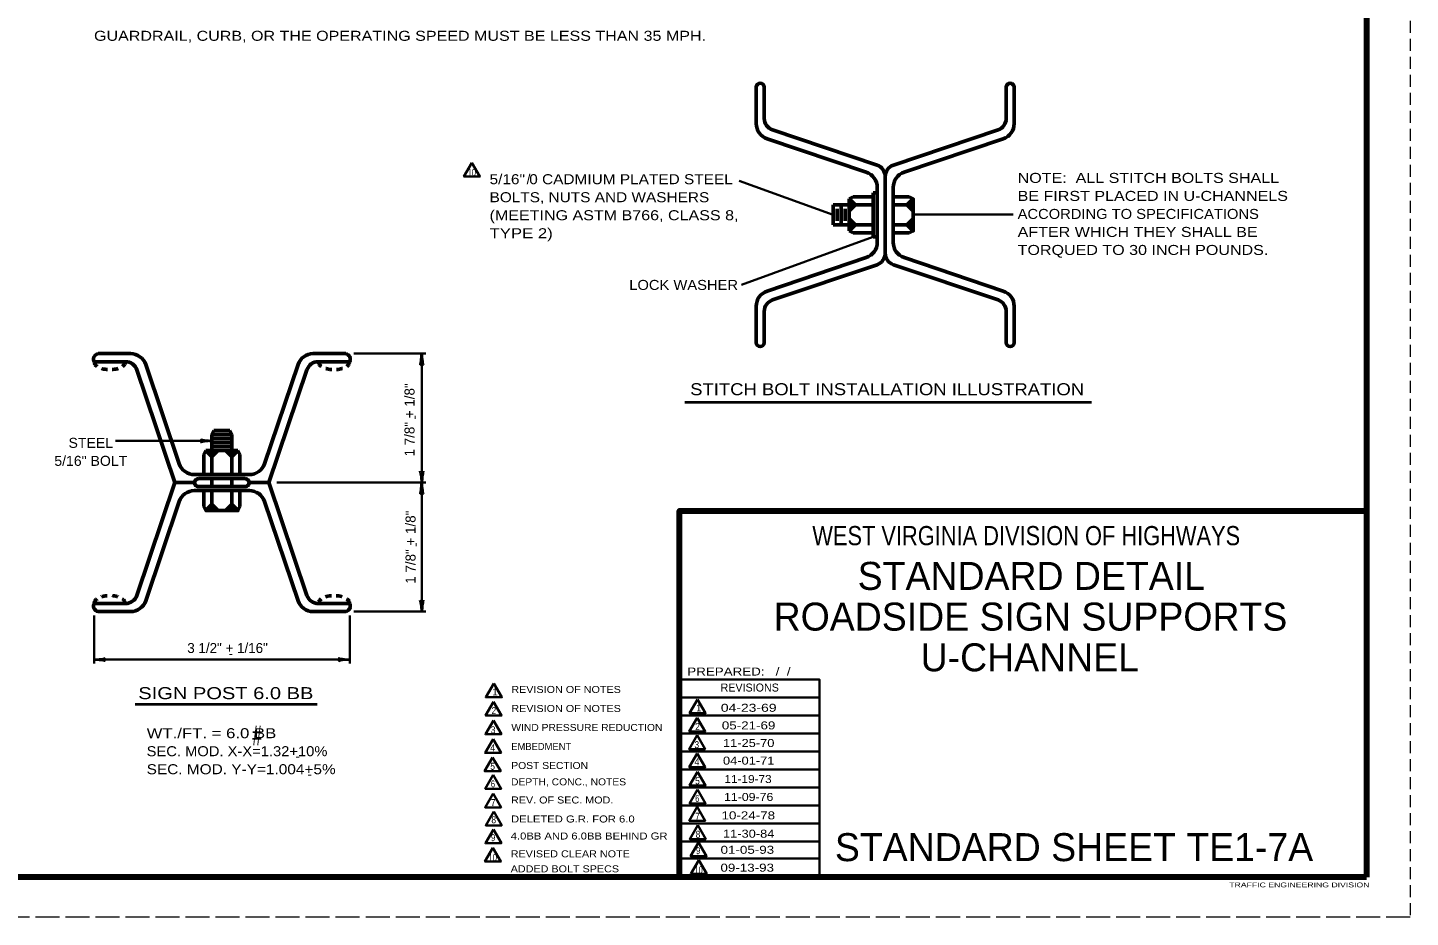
# Model space of a CAD drawing. Extents: x -2 to 678, y -1 to 439.
# Drawn here: x 332.9 to 678.3, y -0.7 to 221.6 of the extents above; entities that cross this region are included whole.
import ezdxf
from ezdxf.enums import TextEntityAlignment as Align

# ---------------------------------------------------------------- set-up
doc = ezdxf.new("R2010")
doc.units = 0
for name, pattern in [('LONG_DASHED', [7.5, 6, -1.5]), ('MEDIUM_DASHED', [4.5, 3, -1.5]), ('SHORT_DASHED', [2.7, 1.5, -1.2])]:
    doc.linetypes.add(name, pattern=pattern)
doc.layers.add('1', color=7, linetype='Continuous', lineweight=53)
doc.layers.add('61', color=7, linetype='Continuous', lineweight=35)

msp = doc.modelspace()

# ---------------------------------------------------------------- linework, layer by layer
at = {"layer": '1', "linetype": 'MEDIUM_DASHED', "lineweight": 13}
msp.add_line((678.327, 439.301), (678.307, -0.719), dxfattribs=at)
at = {"layer": '1'}
for p, q in [((514.897, 197.583), (514.897, 206.711)), ((516.897, 198.865), (516.897, 206.711)), ((577.341, 198.865), (577.341, 206.711)), ((579.341, 197.583), (579.341, 206.711)), ((542.398, 185.438), (517.619, 193.793)), ((545.078, 187.208), (518.939, 196.023)), ((549.161, 187.208), (575.3, 196.023)), ((551.841, 185.438), (576.619, 193.793)), ((547.119, 165.174), (547.119, 184.366)), ((545.119, 180.27), (544.119, 180.27)), ((544.119, 180.27), (544.119, 169.27)), ((545.119, 167.892), (545.119, 181.648)), ((549.119, 167.892), (549.119, 181.648)), ((534.119, 172.27), (534.119, 177.27)), ((535.119, 173.27), (535.119, 176.27)), ((536.119, 172.27), (536.119, 177.27)), ((537.119, 173.27), (537.119, 176.27)), ((538.119, 178.77), (539.119, 179.27)), ((538.119, 170.77), (538.119, 178.77)), ((539.119, 179.27), (544.119, 179.27)), ((549.119, 179.27), (553.119, 179.27)), ((549.119, 177.27), (554.119, 177.27)), ((554.119, 178.77), (553.119, 179.27)), ((554.119, 170.77), (554.119, 178.77)), ((538.119, 170.77), (539.119, 170.27)), ((539.119, 170.27), (544.119, 170.27)), ((549.119, 172.27), (554.119, 172.27)), ((549.119, 170.27), (553.119, 170.27)), ((554.119, 170.77), (553.119, 170.27)), ((545.119, 169.27), (544.119, 169.27)), ((542.398, 164.102), (517.619, 155.747)), ((551.841, 164.102), (576.619, 155.747)), ((545.078, 162.332), (518.939, 153.517)), ((549.161, 162.332), (575.3, 153.517)), ((514.897, 151.957), (514.897, 142.829)), ((516.897, 150.675), (516.897, 142.829)), ((577.341, 150.675), (577.341, 142.829)), ((579.341, 151.957), (579.341, 142.829)), ((358.566, 140.102), (350.438, 140.102)), ((404.193, 140.102), (412.32, 140.102)), ((357.284, 138.102), (349.438, 138.102)), ((369.629, 107.88), (360.127, 136.061)), ((370.711, 112.602), (362.356, 137.38)), ((392.047, 112.602), (400.402, 137.38)), ((393.129, 107.88), (402.632, 136.061)), ((405.475, 138.102), (413.32, 138.102)), ((379.379, 120.88), (378.879, 119.88)), ((378.879, 119.88), (383.879, 119.88)), ((378.879, 118.88), (383.879, 118.88)), ((378.879, 117.88), (383.879, 117.88)), ((379.379, 120.88), (383.379, 120.88)), ((383.379, 120.88), (383.879, 119.88)), ((377.379, 115.88), (376.879, 114.88)), ((376.879, 114.88), (376.879, 109.88)), ((377.379, 115.88), (385.379, 115.88)), ((378.879, 116.88), (383.656, 116.88)), ((385.379, 115.88), (385.879, 114.88)), ((385.879, 114.88), (385.879, 109.88)), ((369.629, 107.88), (360.127, 79.7)), ((369.629, 107.88), (374.577, 107.88)), ((374.502, 109.88), (388.257, 109.88)), ((375.629, 108.88), (387.129, 108.88)), ((378.879, 108.88), (378.879, 106.88)), ((383.879, 108.88), (383.879, 106.88)), ((388.182, 107.88), (393.129, 107.88)), ((393.129, 107.88), (402.632, 79.7)), ((374.502, 105.88), (388.257, 105.88)), ((375.629, 106.88), (387.129, 106.88)), ((376.879, 105.88), (376.879, 101.88)), ((378.879, 105.88), (378.879, 100.88)), ((383.879, 105.88), (383.879, 100.88)), ((385.879, 105.88), (385.879, 101.88)), ((370.711, 103.159), (362.356, 78.38)), ((377.379, 100.88), (376.879, 101.88)), ((377.379, 100.88), (385.379, 100.88)), ((385.379, 100.88), (385.879, 101.88)), ((392.047, 103.159), (400.402, 78.38)), ((357.284, 77.658), (349.438, 77.658)), ((405.475, 77.658), (413.32, 77.658)), ((358.566, 75.658), (350.438, 75.658)), ((404.193, 75.658), (412.32, 75.658))]:
    msp.add_line(p, q, dxfattribs=at)
at = {"layer": '1', "lineweight": 35}
for p, q in [((534.119, 174.77), (510.627, 183.32)), ((554.083, 174.907), (579.083, 174.907)), ((544.119, 169.27), (511.23, 157.299)), ((414.32, 140.102), (432.32, 140.102)), ((378.811, 118.315), (354.811, 118.315)), ((395.129, 107.88), (432.32, 107.88)), ((349.438, 74.658), (349.438, 62.658)), ((413.32, 74.658), (413.32, 62.658)), ((414.32, 75.658), (432.32, 75.658)), ((349.438, 63.658), (413.32, 63.658)), ((530.707, 54.201), (495.727, 54.201)), ((530.707, 49.701), (495.727, 49.701)), ((530.707, 45.201), (495.727, 45.201)), ((530.707, 40.681), (495.727, 40.681)), ((530.707, 36.201), (495.727, 36.201)), ((530.707, 31.721), (495.727, 31.721)), ((530.707, 27.221), (495.727, 27.221)), ((530.707, 22.721), (495.727, 22.721)), ((530.707, 18.201), (495.727, 18.201)), ((530.707, 13.968), (495.727, 13.968))]:
    msp.add_line(p, q, dxfattribs=at)
at = {"layer": '1', "lineweight": 40}
for p, q in [((497.072, 127.975), (598.672, 127.975)), ((359.751, 52.487), (405.219, 52.487))]:
    msp.add_line(p, q, dxfattribs=at)
at = {"layer": '1', "lineweight": 35}
for points in [[(443.859, 187.82), (441.859, 184.356), (445.859, 184.356)], [(449.331, 57.723), (447.331, 54.259), (451.331, 54.259)], [(449.271, 53.147), (447.271, 49.683), (451.271, 49.683)], [(500.227, 53.724), (498.227, 50.26), (502.227, 50.26)], [(449.21, 48.458), (447.21, 44.994), (451.21, 44.994)], [(500.166, 49.148), (498.166, 45.684), (502.166, 45.684)], [(449.124, 43.796), (447.124, 40.332), (451.124, 40.332)], [(500.106, 44.752), (498.106, 41.288), (502.106, 41.288)], [(449.038, 39.22), (447.038, 35.756), (451.038, 35.756)], [(500.166, 40.236), (498.166, 36.772), (502.166, 36.772)], [(449.184, 34.837), (447.184, 31.373), (451.184, 31.373)], [(500.227, 35.66), (498.227, 32.196), (502.227, 32.196)], [(500.227, 31.205), (498.227, 27.741), (502.227, 27.741)], [(449.124, 30.209), (447.124, 26.745), (451.124, 26.745)], [(449.318, 25.706), (447.318, 22.242), (451.318, 22.242)], [(500.166, 26.87), (498.166, 23.405), (502.166, 23.405)], [(449.244, 21.235), (447.244, 17.77), (451.244, 17.77)], [(500.287, 22.294), (498.287, 18.829), (502.287, 18.829)], [(500.47, 17.989), (498.47, 14.525), (502.47, 14.525)], [(449.098, 16.649), (447.098, 13.184), (451.098, 13.184)], [(500.521, 13.557), (498.521, 10.093), (502.521, 10.093)]]:
    msp.add_lwpolyline(points, close=True, dxfattribs=at)
at = {"layer": '1'}
for points in [[(534.119, 177.27), (538.119, 177.27), (544.119, 177.27)], [(534.119, 172.27), (538.119, 172.27), (544.119, 172.27)], [(378.879, 119.88), (378.879, 115.88), (378.879, 109.88)], [(383.879, 119.88), (383.879, 115.88), (383.879, 109.88)]]:
    msp.add_lwpolyline(points, dxfattribs=at)
for points in [[(538.119, 178.77), (538.119, 175.77), (539.619, 177.27)], [(554.119, 175.77), (552.619, 177.27), (554.119, 178.77)], [(538.119, 170.77), (538.119, 173.77), (539.619, 172.27)], [(552.619, 172.27), (554.119, 170.77), (554.119, 173.77)], [(377.379, 115.88), (380.379, 115.88), (378.879, 114.38)], [(385.379, 115.88), (382.379, 115.88), (383.879, 114.38)], [(378.879, 102.38), (377.379, 100.88), (380.379, 100.88)], [(382.379, 100.88), (383.879, 102.38), (385.379, 100.88)]]:
    msp.add_lwpolyline(points, close=True, dxfattribs=at)
at = {"layer": '1', "lineweight": 35}
for points in [[(431.32, 140.102), (431.32, 107.88), (431.32, 75.658)], [(530.707, 9.221), (530.707, 58.681), (495.727, 58.681)]]:
    msp.add_lwpolyline(points, dxfattribs=at)
at = {"layer": '1', "lineweight": 158}
msp.add_lwpolyline([(495.707, 9.261), (495.707, 100.841), (667.367, 100.841)], dxfattribs=at)
at = {"layer": '1'}
for centre, radius, start, end in [((515.897, 206.664), 1.001, 2.66716, 177.33283), ((578.341, 206.664), 1.001, 2.66716, 177.33283), ((518.897, 197.584), 4, 180, 251.36561), ((519.897, 198.865), 3, 180, 251.36548), ((574.341, 198.865), 3, 288.63452, 0), ((575.341, 197.584), 4, 288.63439, 360), ((544.119, 184.366), 3, 0, 71.36649), ((550.119, 184.366), 3, 108.63574, 180), ((541.119, 181.648), 4, 0, 71.36535), ((553.119, 181.648), 4, 108.63465, 180), ((541.119, 167.892), 4, 288.63525, 0), ((553.119, 167.892), 4, 180, 251.36475), ((544.119, 165.174), 3, 288.63393, 0), ((550.119, 165.174), 3, 180, 251.36641), ((518.897, 151.957), 4, 108.63408, 180), ((575.341, 151.957), 4, 0, 71.36592), ((519.897, 150.675), 3, 108.63464, 180), ((574.341, 150.675), 3, 0, 71.36536), ((515.897, 142.876), 1.001, 182.66717, 357.33284), ((578.341, 142.876), 1.001, 182.66717, 357.33284), ((350.703, 138.72), 1.408, 100.85533, 206.01456), ((358.566, 136.102), 4, 18.63408, 90), ((404.193, 136.102), 4, 90, 161.36561), ((412.055, 138.72), 1.408, 333.98544, 79.14467), ((357.284, 135.102), 3, 18.63464, 90), ((405.475, 135.102), 3, 90, 161.36548), ((374.502, 113.88), 4, 198.63525, 270), ((388.257, 113.88), 4, 270, 341.36535), ((375.578, 107.88), 1.001, 87.05408, 272.94592), ((387.181, 107.88), 1.001, 267.05408, 92.94592), ((374.502, 101.88), 4, 90, 161.36475), ((388.257, 101.88), 4, 18.63465, 90), ((357.284, 80.658), 3, 270, 341.36536), ((405.475, 80.658), 3, 198.63452, 270), ((350.703, 77.041), 1.408, 153.98544, 259.14467), ((358.566, 79.658), 4, 270, 341.36592), ((404.193, 79.658), 4, 198.63439, 270), ((412.055, 77.041), 1.408, 280.85533, 26.01456)]:
    msp.add_arc(centre, radius, start, end, dxfattribs=at)
at = {"layer": '1', "lineweight": 40}
for centre, major_axis, ratio, start_param, end_param in [((431.109, 138.982), (0.176, 1.756), 0.07063, 3.1407148, 5.41811), ((431.109, 138.982), (0.176, 1.756), 0.07063, 3.1407148, 5.41811), ((431.597, 139.011), (-0.156, 1.786), 0.122415, 0.8963533, 3.1415927), ((431.597, 139.011), (-0.156, 1.786), 0.122415, 0.8963533, 3.1415927), ((377.719, 118.039), (1.786, 0.156), 0.122415, 0.8963533, 3.1415927), ((377.69, 118.527), (1.756, -0.176), 0.07063, 3.1407148, 5.41811), ((431.044, 108.972), (0.156, -1.786), 0.122415, 0.8963533, 3.1415927), ((431.044, 108.972), (0.156, -1.786), 0.122415, 0.8963533, 3.1415927), ((431.532, 109.001), (-0.176, -1.756), 0.07063, 3.1407148, 5.41811), ((431.532, 109.001), (-0.176, -1.756), 0.07063, 3.1407148, 5.41811), ((431.109, 106.76), (0.176, 1.756), 0.07063, 3.1407148, 5.41811), ((431.109, 106.76), (0.176, 1.756), 0.07063, 3.1407148, 5.41811), ((431.597, 106.789), (-0.156, 1.786), 0.122415, 0.8963533, 3.1415927), ((431.597, 106.789), (-0.156, 1.786), 0.122415, 0.8963533, 3.1415927), ((431.044, 76.75), (0.156, -1.786), 0.122415, 0.8963533, 3.1415927), ((431.532, 76.779), (-0.176, -1.756), 0.07063, 3.1407148, 5.41811), ((350.529, 63.935), (-1.786, -0.156), 0.122415, 0.8963533, 3.1415927), ((350.529, 63.935), (-1.786, -0.156), 0.122415, 0.8963533, 3.1415927), ((350.559, 63.447), (-1.756, 0.176), 0.07063, 3.1407148, 5.41811), ((350.559, 63.447), (-1.756, 0.176), 0.07063, 3.1407148, 5.41811), ((412.229, 63.382), (1.786, 0.156), 0.122415, 0.8963533, 3.1415927), ((412.2, 63.87), (1.756, -0.176), 0.07063, 3.1407148, 5.41811)]:
    msp.add_ellipse(centre, major_axis=major_axis, ratio=ratio, start_param=start_param, end_param=end_param, dxfattribs=at)
at = {"layer": '1', "linetype": 'SHORT_DASHED'}
for centre, major_axis, start_param, end_param in [((353.361, 138.102), (3.923, 0), 3.1415927, 6.2831853), ((409.397, 138.102), (-3.923, 0), 6.2831853, 9.424778), ((353.361, 77.658), (3.923, 0), 6.2831853, 9.424778), ((409.397, 77.658), (-3.923, 0), 3.1415927, 6.2831853)]:
    msp.add_ellipse(centre, major_axis=major_axis, ratio=0.50983, start_param=start_param, end_param=end_param, dxfattribs=at)
at = {"layer": '61', "lineweight": 158}
for p, q in [((667.347, 429.301), (667.367, 9.261)), ((667.367, 9.261), (28.307, 9.281))]:
    msp.add_line(p, q, dxfattribs=at)
at = {"layer": '61', "linetype": 'LONG_DASHED', "lineweight": 13}
msp.add_line((678.307, -0.719), (-1.753, -0.739), dxfattribs=at)

# ---------------------------------------------------------------- texts
at = {"layer": '1'}
for s, height, width, p in [('GUARDRAIL, CURB, OR THE OPERATING SPEED MUST BE LESS THAN 35 MPH.', 2.5, 1.2, (349.431, 218.272)), ('10', 1.75, 0.8, (442.782, 184.508)), ('5/16" 0 CADMIUM PLATED STEEL', 2.5, 1.15, (448.26, 182.443)), ('NOTE:  ALL STITCH BOLTS SHALL', 2.5, 1.2, (580.207, 182.767)), ('BOLTS, NUTS AND WASHERS', 2.5, 1.15, (448.26, 177.943)), ('BE FIRST PLACED IN U-CHANNELS', 2.5, 1.2, (580.207, 178.267)), ('ACCORDING TO SPECIFICATIONS', 2.5, 1.1, (580.207, 173.767)), ('(MEETING ASTM B766, CLASS 8,', 2.5, 1.2, (448.26, 173.443)), ('TYPE 2)', 2.5, 1.25, (448.26, 168.943)), ('AFTER WHICH THEY SHALL BE', 2.5, 1.2, (580.207, 169.267)), ('TORQUED TO 30 INCH POUNDS.', 2.5, 1.2, (580.207, 164.767)), ('PREPARED:   /  /  ', 1.998, 1.25, (497.667, 59.681)), ('REVISION OF NOTES', 1.75, 1.15, (453.696, 55.331)), ('REVISION OF NOTES', 1.75, 1.15, (453.696, 50.581)), ('2', 1.75, 0.9, (448.74, 50.038)), ('WT./FT. = 6.0 BB', 2.5, 1.25, (362.586, 44.024)), ('3', 1.75, 0.9, (448.559, 45.229)), ('WIND PRESSURE REDUCTION', 1.75, 1.1, (453.696, 45.831)), ('2', 1.75, 0.9, (499.635, 46.039)), ('SEC. MOD. X-X=1.32+10%', 2.5, 1.1, (362.586, 39.524)), ('4', 1.75, 0.95, (448.412, 40.735)), ('3', 1.75, 0.9, (499.455, 41.523)), ('POST SECTION', 1.75, 1.1, (453.696, 36.331)), ('4', 1.75, 0.95, (499.455, 37.249)), ('SEC. MOD. Y-Y=1.004+5%', 2.5, 1.15, (362.586, 35.024)), ('5', 1.75, 0.9, (448.446, 36.125)), ('6', 1.75, 0.8, (448.593, 31.729)), ('DEPTH, CONC., NOTES', 1.75, 1.1, (453.623, 32.24)), ('5', 1.75, 0.9, (499.635, 32.492)), ('7', 1.75, 0.9, (448.593, 27.054)), ('REV. OF SEC. MOD.', 1.75, 1.15, (453.623, 27.71)), ('6', 1.75, 0.8, (499.635, 28.096)), ('8', 1.75, 0.9, (448.714, 22.758)), ('DELETED G.R. FOR 6.0', 1.75, 1.2, (453.623, 22.96)), ('7', 1.75, 0.9, (499.635, 23.641)), ('8', 1.75, 0.9, (499.756, 19.125)), ('9', 1.75, 0.8, (448.64, 18.286)), ('4.0BB AND 6.0BB BEHIND GR', 1.75, 1.2, (453.55, 18.708)), ('10', 1.75, 0.8, (448.022, 13.336)), ('REVISED CLEAR NOTE', 1.75, 1.15, (453.55, 14.257)), ('9', 1.75, 0.8, (499.866, 15.041)), ('ADDED BOLT SPECS', 1.75, 1.15, (453.55, 10.507)), ('10', 1.75, 0.8, (499.444, 10.245)), ('TRAFFIC ENGINEERING DIVISION', 1.2, 1.35, (633.087, 6.761))]:
    msp.add_text(s, height=height, dxfattribs=dict(at, width=width)).set_placement(p)
for s, height, p in [('/', 2.5, (457.996, 182.425)), ('STANDARD DETAIL', 6.993, (583.624, 81.081)), ('ROADSIDE SIGN SUPPORTS', 6.993, (583.41, 70.906)), ('3 1/2" + 1/16"', 2.5, (382.802, 65.306)), ('U-CHANNEL', 6.993, (583.243, 60.73)), ('-', 2.5, (383.624, 63.992)), ('-', 2.5, (400.304, 38.306)), ('-', 2.5, (403.343, 33.81))]:
    msp.add_text(s, height=height, dxfattribs=at).set_placement(p, align=Align.CENTER)
for s, height, width, p in [('LOCK WASHER', 2.5, 1.1, (496.757, 156.028)), ('STITCH BOLT INSTALLATION ILLUSTRATION', 3, 1.15, (547.602, 129.72)), ('STEEL', 2.5, 1.05, (348.623, 116.569)), ('5/16" BOLT', 2.5, 1.05, (348.623, 112.069)), ('WEST VIRGINIA DIVISION OF HIGHWAYS', 4.795, 0.85, (582.355, 92.241)), ('SIGN POST 6.0 BB', 3, 1.25, (382.374, 53.779)), ('04-23-69', 2, 1.3, (513.007, 50.621)), ('#', 5, 0.65, (390.156, 42.217)), ('05-21-69', 2, 1.25, (512.987, 46.221)), ('11-25-70', 2, 1.2, (513.007, 41.821)), ('04-01-71', 2, 1.2, (513.007, 37.421)), ('11-19-73', 2, 1.1, (512.847, 32.821)), ('11-09-76', 2, 1.15, (513.007, 28.341)), ('10-24-78', 2, 1.25, (512.907, 23.741)), ('11-30-84', 2, 1.2, (513.007, 19.161)), ('01-05-93', 2, 1.25, (512.676, 15.141)), ('09-13-93', 2, 1.25, (512.64, 10.667))]:
    msp.add_text(s, height=height, dxfattribs=dict(at, width=width)).set_placement(p, align=Align.CENTER)
for s, p in [('1 7/8" + 1/8"', (429.512, 123.558)), ('-', (430.642, 124.195)), ('1 7/8" + 1/8"', (429.773, 91.746)), ('-', (430.904, 92.384))]:
    msp.add_text(s, height=2.5, rotation=90, dxfattribs=at).set_placement(p, align=Align.CENTER)
for s, height, p in [('1', 1.75, (448.98, 54.735)), ('REVISIONS', 1.998, (505.987, 55.681)), ('1', 1.75, (499.876, 50.736)), ('EMBEDMENT', 1.75, (453.696, 41.081)), ('STANDARD SHEET TE1-7A', 6.993, (534.547, 13.301))]:
    msp.add_text(s, height=height, dxfattribs=at).set_placement(p)

doc.saveas('drawing.dxf')
